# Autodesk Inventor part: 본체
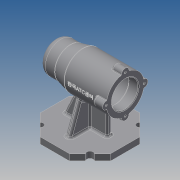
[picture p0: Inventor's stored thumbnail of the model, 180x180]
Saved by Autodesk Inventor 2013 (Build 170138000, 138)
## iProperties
Created: 2019-12
Part Number: 본체
Material: 일반
Document SubType Name: Modeling
Designer: Administrator
Density: 1 g/cm^3
Author: Administrator
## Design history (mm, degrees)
sketch "스케치1"
  geometry: L1 (-56, 0)-(56, 0); L2 (-56, 0)-(-56, 25); L3 (-56, 25)-(-31, 25); L4 (-31, 25)-(-11, 30); L5 (-11, 30)-(56, 30); L6 (56, 30)-(56, 0); 2 further points
  constraints: 12 end point, 2 parallel, 2 perpendicular, 1 coincident, 1 horizontal, 1 midpoint
  dimensions: "d0" = 112 distance of L1.start L1.end; "d2" = 25 distance of L2.end L3.end; "d3" = 45 distance from line of L2 L4.end; "d4" = 50 diameter of L3 L1; "d5" = 60 diameter of L5 L1
revolve "회전1" sketch "스케치1" stored, may be unused: angle "d6" = 90 deg
node "작업 평면1"
sketch "스케치2"
  geometry: L1 (23.196, 56)-(56, 23.196); L2 (56, 23.196)-(56, -23.196); L3 (56, -23.196)-(23.196, -56); L4 (23.196, -56)-(-23.196, -56); L5 (-23.196, -56)-(-56, -23.196); L6 (-56, -23.196)-(-56, 23.196); L7 (-56, 23.196)-(-23.196, 56); L8 (-23.196, 56)-(23.196, 56); 3 further points
  constraints: 16 end point, 1 coincident, 1 midpoint, 1 vertical alignment, 17 other
  dimensions: "d8" = 56 distance from line of L2 point (0, 0)
extrude "돌출1" join sketch "스케치2" distance "d9" = 10; taper "d10" = 0 deg
sketch "스케치3"
  geometry: L1 (56, 25)-(56, -25) reference; L2 (56, -25)-(31, -25) reference; L3 (31, -25)-(11, -30) reference; L4 (11, -30)-(-56, -30) reference; L5 (-56, -30)-(-56, 30) reference; L6 (-56, 30)-(11, 30) reference; L7 (11, 30)-(31, 25) reference; L8 (31, 25)-(56, 25) reference; L9 (56, -70)-(56, -80) reference; L10 (56, -80)-(-56, -80) reference; L11 (-56, -80)-(-56, -70) reference; L12 (-56, -70)-(56, -70) reference; L13 (38, -70)-(5.358, 0); L14 (5.358, 0)-(-31, 0); L15 (-31, 0)-(-31, -70); L16 (-31, -70)-(38, -70); 1 further point
  constraints: 8 end point, 3 point on line, 1 collinear, 1 parallel, 1 perpendicular
  dimensions: "d11" = 115 deg angle of L13 L12; "d12" = 25 distance between parallel lines of L11 L15; "d13" = 18 distance from line of L9 L13.start
extrude "돌출2" join sketch "스케치3" stored distance "d14" = 8; taper "d15" = 0 deg
sketch "스케치4"
  geometry: L1 (-56, -80)-(-56, -70) reference; L2 (-56, -70)-(-4, -70) reference; L3 (-4, -70)-(-4, -29.732) reference; L4 (4, -29.732)-(4, -70) reference; L5 (4, -70)-(56, -70) reference; L6 (56, -70)-(56, -80) reference; L7 (56, -80)-(-56, -80) reference; L8 (-36, -70)-(-18.979, -23.234); A1 r 30 centre (0, 0) between (4, -29.732) and (-4, -29.732) reference; 1 further point
  constraints: 2 end point, 1 point on circle, 1 point on line
  dimensions: "d16" = 20 distance from line of L8.start L1; "d17" = 110 deg angle of L8 L2
feature "리브1" sketch "스케치4" dims "d18" = 1, "d19" = 8, "d20" = 0, "d21" = 0, "d22" = 1, "d23" = 1
sketch "스케치5"
  geometry: C1 r 6 at (-30, 0); 1 further point
  constraints: 2 horizontal alignment, 1 centre point, 1 other
  dimensions: "d24" = 12 diameter of C1
extrude "돌출3" join sketch "스케치5" distance "d25" = 16; taper "d26" = 0 deg
sketch "스케치6"
  geometry: A1 r 6 centre (0, 0) between (0.6, 5.97) and (0.6, -5.97) reference
hole "구멍1" sketch "스케치6" at (0, 0) diameter "d27" = 3.242; stored, may be unused: countersink angle "d31" = 90 deg, drill point angle "d33" = 118 deg; dims "d28" = 8, "d29" = 4, "d30" = 2, "d32" = 11
sketch "스케치7"
  geometry: L1 (23.196, -56)-(56, -23.196) reference; L2 (56, 23.196)-(23.196, 56) reference; L3 (-23.196, 56)-(-56, 23.196) reference; L4 (-56, -23.196)-(-23.196, -56) reference; C1 r 5 at (-39.598, 39.598); C2 r 5 at (-39.598, -39.598); C3 r 5 at (39.598, 39.598); C4 r 5 at (39.598, -39.598); 1 further point
  constraints: 4 centre point, 4 midpoint
  dimensions: "d37" = 10 diameter of C1; "d38" = 10 diameter of C2; "d39" = 10 diameter of C3; "d40" = 10 diameter of C4
extrude "돌출4" cut sketch "스케치7" stored distance "d41" = 16; taper "d42" = 0 deg
sketch "스케치8"
  geometry: L1 (56, 25)-(56, -25) reference; L2 (56, -25)-(31, -25) reference; L3 (31, -25)-(18.476, -28.131) reference; L4 (18.476, -28.131)-(38, -70) reference; L5 (38, -70)-(56, -70) reference; L6 (56, -70)-(56, -80) reference; L7 (56, -80)-(-56, -80) reference; L8 (-56, -80)-(-56, -70) reference; L9 (-56, -70)-(-31, -70) reference; L10 (-31, -70)-(-31, -30) reference; L11 (-31, -30)-(-40, -30) reference; L12 (-40, -30)-(-40, -36) reference; L13 (-40, -36)-(-56, -36) reference; L14 (-56, -36)-(-56, -31.621) reference; L15 (-56, -31.621)-(-45, -31.621) reference; L16 (-45, -31.621)-(-44.026, -30) reference; L17 (-44.026, -30)-(-45, -28.379) reference; L18 (-45, -28.379)-(-56, -28.379) reference; L19 (-56, -28.379)-(-56, 28.379) reference; L20 (-56, 28.379)-(-45, 28.379) reference; L21 (-45, 28.379)-(-44.026, 30) reference; L22 (-44.026, 30)-(-45, 31.621) reference; L23 (-45, 31.621)-(-56, 31.621) reference; L24 (-56, 31.621)-(-56, 36) reference; L25 (-56, 36)-(-40, 36) reference; L26 (-40, 36)-(-40, 30) reference; L27 (-40, 30)-(11, 30) reference; L28 (11, 30)-(31, 25) reference; L29 (31, 25)-(56, 25) reference; L30 (50, 0)-(-56, 0); L31 (50, 0)-(50, 10.5); L32 (50, 10.5)-(47, 10.5); L33 (47, 10.5)-(47, 16); L34 (47, 16)-(43, 16); L35 (43, 16)-(43, 17.5); L36 (43, 17.5)-(25, 17.5); L37 (25, 17.5)-(25, 21); L38 (25, 21)-(13, 21); L39 (13, 21)-(13, 24); L40 (13, 24)-(-41, 24); L41 (-41, 24)-(-41, 21); L42 (-41, 21)-(-56, 21); L43 (-56, 21)-(-56, 0); 1 further point
  constraints: 28 end point, 12 parallel, 2 perpendicular, 2 point on line, 1 collinear, 1 midpoint
  dimensions: "d43" = 15 distance between parallel lines of L43 L41; "d45" = 54 distance between parallel lines of L41 L39; "d46" = 3 distance of L31.end L32.end; "d47" = 12 distance of L37.end L38.end; "d48" = 18 distance of L35.end L36.end; "d49" = 4 distance of L33.end L34.end; "d50" = 42 diameter of L42 L30; "d51" = 48 diameter of L40 L30; "d52" = 42 diameter of L38 L30; "d53" = 21 diameter of L32 L30; "d54" = 32 diameter of L34 L30; "d55" = 35 diameter of L36 L30
revolve "회전2" sketch "스케치8" stored, may be unused: angle "d56" = 90 deg
fillet "모깎기1" dims "d57" = 0.3
fillet "모깎기2" dims "d58" = 3
chamfer "모따기1" distance "d59" = 1; stored, may be unused: second distance "d60" = 2, angle "d61" = 45 deg
fillet "모깎기3" dims "d62" = 3
fillet "모깎기4" dims "d63" = 1
fillet "모깎기5" dims "d64" = 10
fillet "모깎기6" dims "d65" = 3
node "작업 평면2"
sketch "스케치9"
  geometry: L1 (-10.631, -29.732)-(-10.631, -29.732) reference; L2 (-10.631, -29.732)-(-4, -29.732) reference; L3 (-4, -29.732)-(-4, -23.234) reference; L4 (-4, -23.234)-(4, -23.234) reference; L5 (4, -23.234)-(4, -29.732) reference; L6 (4, -29.732)-(31, -29.732) reference; L7 (31, -29.732)-(31, -29.732) reference; L8 (31, -29.732)-(4, -29.732) reference; L9 (4, -29.732)-(4, -23.234) reference; L10 (4, -23.234)-(-4, -23.234) reference; L11 (-4, -23.234)-(-4, -29.732) reference; L12 (-4, -29.732)-(-10.631, -29.732) reference; L13 (56, -6.771)-(43, -6.771) reference; L14 (56, -29.226)-(56, -6.771) reference; L15 (43, -29.226)-(56, -29.226) reference; L16 (39, -29.871)-(39, -29.871) reference; L17 (56, -29.226)-(43, -29.226) reference; L18 (56, -6.771)-(56, -29.226) reference; L19 (43, -6.771)-(56, -6.771) reference; L20 (39, 2.779)-(39, -2.779) reference; L21 (56, 6.771)-(43, 6.771) reference; L22 (56, 29.226)-(56, 6.771) reference; L23 (43, 29.226)-(56, 29.226) reference; L24 (39, 29.871)-(39, 29.871) reference; L25 (56, 29.226)-(43, 29.226) reference; L26 (56, 6.771)-(56, 29.226) reference; L27 (43, 6.771)-(56, 6.771) reference; L28 (39, -2.779)-(39, 2.779) reference; 2 further points
  constraints: 1 horizontal alignment, 9 other
  dimensions: "d67" = 41 distance from line of L22 point (15, 0)
feature "엠보싱1" sketch "스케치9" dims "d0" = 112, "d2" = 25, "d3" = 45, "d4" = 50, "d5" = 60, "d68" = 0.5, "d69" = 0
fillet "모깎기7" dims "d70" = 3
fillet "모깎기8" dims "d71" = 3
fillet "모깎기9" dims "d72" = 3
node "솔리드1"
mirror "대칭1"
pattern_circular "원형 패턴1" dims angle "d35" = 360 deg
node "투영된 루프1"
node "절단 모서리 투영1"
node "절단 모서리 투영2"
node "절단 모서리 투영3"
other parameters: "d66" = -98.5
